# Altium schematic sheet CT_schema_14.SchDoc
size 274 x 160 mm
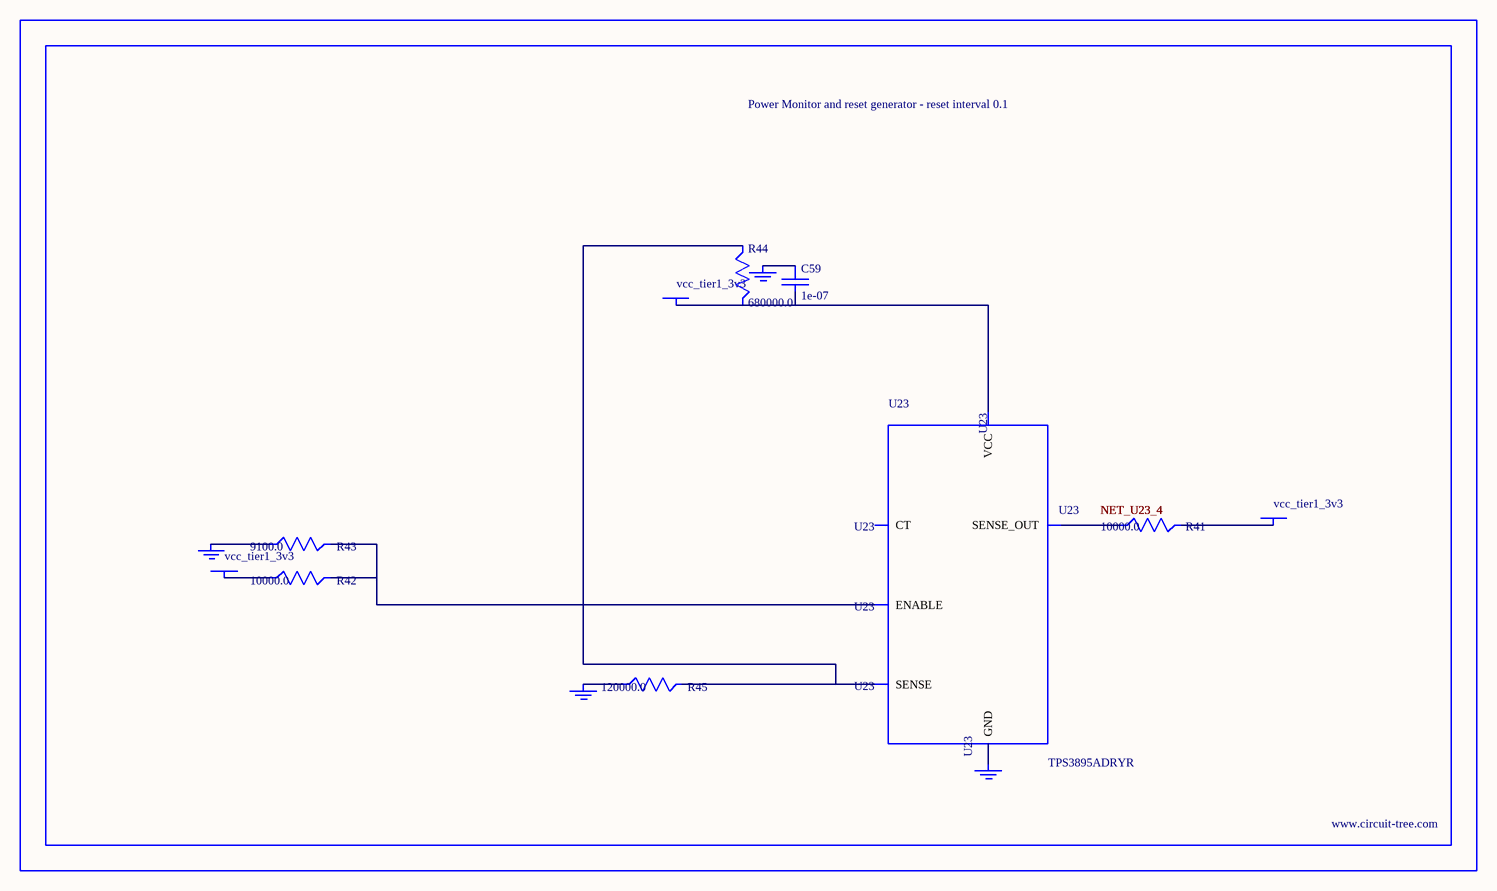
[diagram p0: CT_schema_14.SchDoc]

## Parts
BORDER13  (no value)
C59  1e-07  [C0402]
GND_INSTANCE_13_0  (no value)
GND_INSTANCE_13_1  (no value)
GND_INSTANCE_13_2  (no value)
GND_INSTANCE_13_3  (no value)
POWER_INSTANCE_13_0  vcc_tier1_3v3
POWER_INSTANCE_13_1  vcc_tier1_3v3
POWER_INSTANCE_13_2  vcc_tier1_3v3
R41  10000.0  [R0603]
R42  10000.0  [R0603]
R43  9100.0  [R0603]
R44  680000.0  [R0603]
R45  120000.0  [R0603]
U23  TPS3895ADRYR  [SON-6]

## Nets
NetC59_1: C59.1 GND_INSTANCE_13_2.0(GND)
NetC59_2: C59.2 POWER_INSTANCE_13_2.0(PWR) R44.2 U23.6(VCC)
NetGND_INSTANCE_13_0_0: GND_INSTANCE_13_0.0(GND) R43.1
NetGND_INSTANCE_13_1_0: GND_INSTANCE_13_1.0(GND) R45.1
NetGND_INSTANCE_13_3_0: GND_INSTANCE_13_3.0(GND) U23.2(GND)
NetPOWER_INSTANCE_13_0_0: POWER_INSTANCE_13_0.0(PWR) R42.1
NetPOWER_INSTANCE_13_1_0: POWER_INSTANCE_13_1.0(PWR) R41.2
NetR41_1: R41.1 U23.4(SENSE_OUT)
NetR42_2: R42.2 R43.2 U23.1(ENABLE)
NetR44_1: R44.1 R45.2 U23.3(SENSE)

Not connected (* = marked no-connect by the designer): U23 5(CT)

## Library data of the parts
BORDER13 = BORDER_PAGE13
C59 = C0402C104K3RACTU
GND_INSTANCE_13_0-GND_INSTANCE_13_3 = GND
POWER_INSTANCE_13_0-POWER_INSTANCE_13_2 = PWR
R41 R42 = RC0603JR-0710KL
R43 = RC0603JR-079K1L
R44 = RC0603JR-07680KL
R45 = RC0603JR-07120KL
